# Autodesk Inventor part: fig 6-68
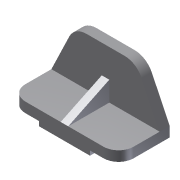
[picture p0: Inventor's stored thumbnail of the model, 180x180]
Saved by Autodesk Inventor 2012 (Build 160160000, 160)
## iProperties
Shininess: 77.0
Length Units: 11269
Angle Units: 11279
Time Units: 11290
Mass Units: 11283
Length Display Precision: 3
Angle Display Precision: 2
Created: 2001-12
Part Number: fig 6-68
Document SubType Name: Modeling
Designer: Renu Muthoo
Density: 1 g/cm^3
Material: Default
Density: 0.0
Volumn: 0.0
Area: 0.0
PropertySet Name: Model Information
Control State: 0
Master: False
Checked Out: False
Author: Renu Muthoo
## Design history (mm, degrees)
node "Sketch1"
sketch "Sketch2"
  geometry: L1 (-67.219, 19.116)-(148.781, 19.116); L2 (148.781, 19.116)-(148.781, -0.884); L3 (-67.219, -0.884)-(-67.219, 19.116); L4 (-10.219, -0.884)-(-10.219, -9.884); L5 (-10.219, -9.884)-(91.781, -9.884); L6 (91.781, -9.884)-(91.781, -0.884); L7 (148.781, -0.884)-(91.781, -0.884); L8 (-10.219, -0.884)-(-67.219, -0.884)
  constraints: 16 end point, 5 parallel, 4 perpendicular, 2 equal length, 1 horizontal
  dimensions: "d0" = 102 distance of L4.end L5.end; "d1" = 57 distance of L4.start L3.start; "d2" = 29 distance between parallel lines of L1 L5; "d3" = 20 distance of L1.end L2.end
extrude "Extrusion1" new body sketch "Sketch2" distance "d4" = 102; taper "d5" = 0 deg
sketch "Sketch3"
  geometry: L1 (67.219, -19.116)-(-148.781, -19.116) reference; L2 (67.219, -19.116)-(31.475, -93.564); L3 (-2.781, -115.116)-(-78.781, -115.116); L4 (-113.038, -93.564)-(-148.781, -19.116); A1 r 38 centre (-2.781, -77.116) between (-2.781, -115.116) and (31.475, -93.564); A2 r 38 centre (-78.781, -77.116) between (-113.038, -93.564) and (-78.781, -115.116)
  constraints: 6 end point, 4 point on circle, 4 tangent, 2 centre point, 1 equal length, 1 equal radius, 1 parallel
  dimensions: "d6" = 96 distance between parallel lines of L3 L1; "d7" = 38 radius of A1; "d8" = 76 distance of A2.centre A1.centre
extrude "Extrusion2" join sketch "Sketch3" distance "d9" = 20; taper "d10" = 0 deg
fillet "Fillet1" dims "d11" = 30
workplane "Work Plane1"
sketch "Sketch7"
  geometry: L1 (0, -82)-(-39.557, 0)
  constraints: 2 end point
feature "Rib4" sketch "Sketch7" dims "d37" = 1, "d38" = 15, "d39" = 0
body "Solid1"
other parameters: "d12" = -108
